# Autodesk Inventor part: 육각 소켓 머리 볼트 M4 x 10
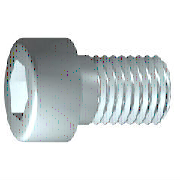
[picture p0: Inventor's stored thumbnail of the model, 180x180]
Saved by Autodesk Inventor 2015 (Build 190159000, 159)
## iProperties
IsCustomPart: 1
Created: 2012-02
Part Number: 육각 소켓 머리 볼트 M4 x 10
Material: 스테인리스강
Description: 6각 소켓 머리 캡 나사
Document SubType Name: Modeling
Standard: ISO 4762
Designer: mduedu
Standard Revision: Fourth edition 2004-03-01
Standards Organization: ISO
Language: ko-KR
Size Designation: M4 x 10
Categories: <MemberInstance><Categories><Category DisplayName="조임쇠" InternalName="e4da775c-781d-43d5-af7c-5136215cf5a6" Mnemonic="FSTN"><Category DisplayName="볼트" InternalN
Density: 8.08 g/cm^3
Mass: 2.09412 g
Surface Area: 3.0572 cm^2
Volume: 0.259174 cm^3
Appearance: 반광택
Author: mduedu
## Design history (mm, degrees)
sketch "스케치1"
  geometry: L1 (-1, 0)-(10, 0); L2 (10, 0)-(10, 2); L3 (10, 2)-(1.75, 2); L4 (1.75, 2)-(1.32, 2); L5 (1.32, 2)-(0, 2); L6 (0, 2)-(0, 3.5); L7 (0, 3.5)-(-4, 3.5); L8 (-4, 3.5)-(-4, 1.732); L9 (-4, 1.732)-(-2, 1.732); L10 (-2, 1.732)-(-1, 0); L11 (-6.8, 0)-(12.8, 0) reference; L12 (0, -0.7)-(0, 4.2) reference; L13 (1.75, 2)-(0, 2)
  constraints: 22 end point, 6 parallel, 2 collinear, 2 perpendicular, 1 horizontal, 1 point on line
  dimensions: "d1" = 8.25 distance from line of L3.end L2 (= GEL); "d2" = 0.42952 distance of L4.end L3.end (computed from GAL); "d3" = 4 distance between parallel lines of L8 L6 (= KOH); "d4" = 2 distance of L8.end L9.end (= INTI); "d5" = 60 deg angle of L10 L1; "d6" = 4 diameter of L3 L1 (= GD); "d7" = 4 diameter of L5 L1 (= BDM); "d8" = 3.4641 diameter of L9 L1 (= 1.1547 x SW); "d9" = 7 diameter of L7 L1 (= KOD); "d26" = 10 distance between parallel lines of L12 L2 (= NLG)
revolve "본체" sketch "스케치1" stored, may be unused: angle "d10" = 90 deg
sketch "스케치2"
  geometry: L1 (0, -4.9)-(0, 4.9) reference; L2 (-4.9, 0)-(4.9, 0) reference; L3 (1.732, 0)-(0.866, -1.5); L4 (0.866, -1.5)-(-0.866, -1.5); L5 (-0.866, -1.5)-(-1.732, 0); L6 (-1.732, 0)-(-0.866, 1.5); L7 (-0.866, 1.5)-(0.866, 1.5); L8 (0.866, 1.5)-(1.732, 0); 2 further points
  constraints: 12 end point, 1 coincident, 1 horizontal alignment, 1 point on line, 12 other
extrude "슬롯" join sketch "스케치2" stored distance "d11" = 10; taper "d12" = 0 deg
workplane "Work Plane1"
fillet "Fillet2" dims "d30" = 0.1 (= R)
body "Solid1"
fillet "모깎기1" dims "d17" = 0.4 (= RR)
feature "스레드" dims "d13" = 8.25 (= GEL), "d14" = 0
chamfer "모따기1" distance "d15" = 0.42941 (= -0.5 x SPD + 0.5 x GD); stored, may be unused: second distance "d16" = 0.42941 (= GUL), angle "d27" = 45 deg
other parameters: "GD" = 4 [user parameter; used in 2 equation terms], "NLG" = 10 [user parameter; used in 1 equation term], "GEL" = 8.25 [user parameter; used in 2 equation terms], "KOD" = 7 [user parameter; used in 1 equation term], "KOH" = 4 [user parameter; used in 1 equation term], "INTI" = 2 [user parameter; used in 1 equation term], "GAL" = 0.42941 (= 0.61345 x PTC) [user parameter; used in 1 equation term], "GUL" = 0.42941 (= 0.61345 x PTC) [user parameter; used in 1 equation term], "BDM" = 4 (= NND) [user parameter; used in 1 equation term], "SW" = 3 [user parameter; used in 2 equation terms], "RR" = 0.4 [user parameter; used in 1 equation term], "SPD" = 3.14117 (= NND - 1.2269 x PTC) [user parameter; used in 1 equation term], "d19" = 0, "d28" = 0, "d29" = 0, "R" = 0.1 [user parameter; used in 1 equation term], "TOA" = 30 deg [user parameter], "GD1" = 3.14117 (= THREADDIA - 1.2269 x PTC) [user parameter], "THREADDIA" = 4 [user parameter; used in 1 equation term], "FAWI" = 45 deg [user parameter], "TPU" = 14.28571 (computed from PTC) [user parameter], "PTC" = 0.7 [user parameter; used in 5 equation terms], "NND" = 4 [user parameter; used in 2 equation terms], "E0" = 3.465 (= 1.155 x SW) [user parameter]
